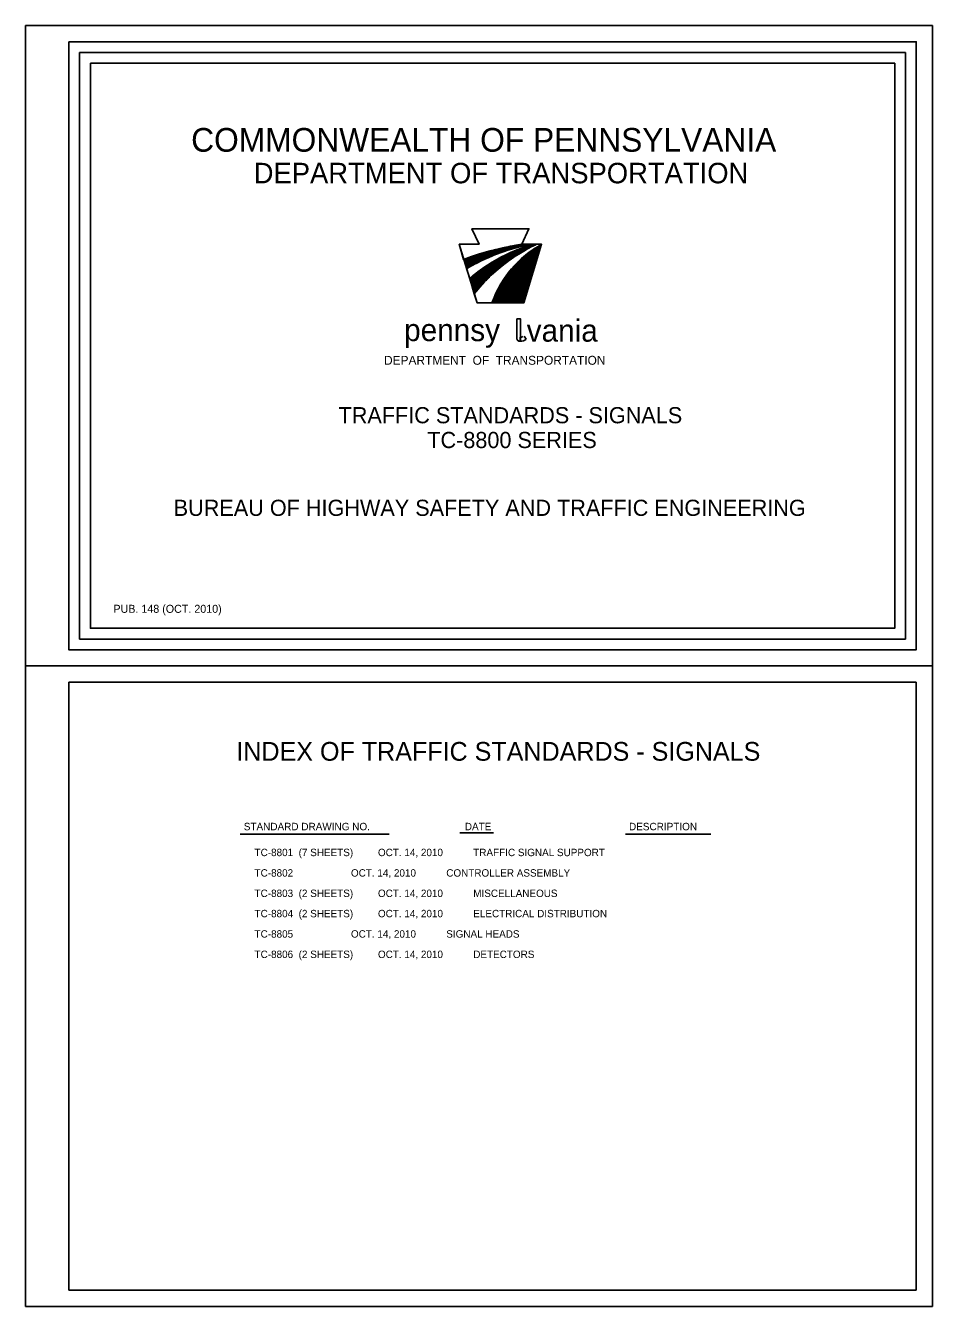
# Model space of a CAD drawing. Extents: x -1746 to -905, y 22 to 1210.
import ezdxf

# ---------------------------------------------------------------- set-up
doc = ezdxf.new("R2010")
doc.units = 0
for name, color, linetype in [('1', 7, 'Continuous'), ('2', 7, 'Continuous'), ('PLT-BNDY', 7, 'Continuous')]:
    doc.layers.add(name, color=color, linetype=linetype)

msp = doc.modelspace()

# ---------------------------------------------------------------- linework, layer by layer
at = {"layer": '1'}
for p, q in [((-1325.5, 1007.3), (-1332.2, 1021.7)), ((-1332.2, 1021.7), (-1279.3, 1021.7)), ((-1279.3, 1021.7), (-1286, 1007.3)), ((-1327.3, 952.9), (-1344, 1007.3)), ((-1344, 1007.3), (-1325.5, 1007.3)), ((-1286, 1007.3), (-1267.6, 1007.3)), ((-1267.6, 1007.3), (-1284.2, 952.9)), ((-1284.2, 952.9), (-1327.3, 952.9)), ((-1706.1, 601.2), (-920.1, 601.2)), ((-1706.1, 37.2), (-1706.1, 601.2)), ((-920.1, 601.2), (-920.1, 37.2)), ((-920.1, 37.2), (-1706.1, 37.2))]:
    msp.add_line(p, q, dxfattribs=at)
for points in [[(-1706.1, 1195.2), (-920.1, 1195.2), (-920.1, 631.2), (-1706.1, 631.2)], [(-1696.1, 1185.2), (-930.1, 1185.2), (-930.1, 641.2), (-1696.1, 641.2)], [(-1686.1, 1175.2), (-940.1, 1175.2), (-940.1, 651.2), (-1686.1, 651.2)], [(-1286, 1007.3), (-1279.3, 1021.7), (-1332.2, 1021.7), (-1325.5, 1007.3), (-1344, 1007.3), (-1340.1, 993.2), (-1332.6, 996), (-1326.2, 998.1), (-1320.9, 999.7), (-1315.2, 1001.2), (-1311, 1002.3), (-1302.4, 1004.3), (-1293.9, 1006), (-1288.6, 1006.8)], [(-1286, 1007.3), (-1289.7, 1006.7), (-1293.9, 1005.9), (-1299, 1004.9), (-1303.4, 1004), (-1308.4, 1002.9), (-1314.9, 1001.2), (-1321.6, 999.4), (-1327.3, 997.6), (-1333.2, 995.7), (-1338, 993.9), (-1339.8, 993.2), (-1337, 984.8), (-1332.7, 987.4), (-1328, 989.8), (-1324.3, 991.7), (-1319.8, 993.9), (-1315.3, 995.8), (-1310.4, 997.8), (-1306.5, 999.3), (-1301.8, 1001), (-1297.2, 1002.4), (-1291.9, 1004), (-1287.6, 1005.2), (-1282.8, 1006.3), (-1279.5, 1007.3)], [(-1279.5, 1007.3), (-1288.1, 1005.1), (-1299.7, 1001.6), (-1309.4, 998.2), (-1318, 994.7), (-1327.6, 990.2), (-1335.1, 986.1), (-1337.3, 984.8), (-1334.2, 975.5), (-1329.9, 979.3), (-1326.8, 981.7), (-1322.8, 984.5), (-1319.5, 986.8), (-1315.6, 989.3), (-1311, 992), (-1305.3, 995.3), (-1300.1, 997.9), (-1294.3, 1000.7), (-1291, 1001.9), (-1286.4, 1003.8), (-1280.6, 1005.7), (-1275.9, 1007.3)], [(-1275.9, 1007.3), (-1281, 1005.6), (-1285.3, 1004.1), (-1290.3, 1002.1), (-1295.5, 1000), (-1300.7, 997.6), (-1306.6, 994.5), (-1312.4, 991.2), (-1317.6, 988), (-1322.4, 984.9), (-1327.4, 981.1), (-1331.1, 978.3), (-1334.2, 975.5), (-1330.1, 961.5), (-1324.9, 967.6), (-1320.4, 972.5), (-1316.2, 976.7), (-1311.3, 981.5), (-1307.1, 985), (-1302.4, 988.9), (-1297.7, 992.5), (-1293.5, 995.4), (-1288.8, 998.3), (-1284.1, 1001.1), (-1280.8, 1003.1), (-1276.6, 1005.4), (-1272.2, 1007.3)], [(-1272.2, 1007.3), (-1276.2, 1005.6), (-1282, 1002.5), (-1289.2, 998.1), (-1297.3, 992.7), (-1304.2, 987.5), (-1308, 984.4), (-1314.3, 978.7), (-1318.1, 974.9), (-1323.2, 969.5), (-1326.5, 965.7), (-1330.1, 961.5), (-1327.3, 952.9), (-1313.4, 952.9), (-1312.6, 955.3), (-1309.9, 961.9), (-1308.2, 965.3), (-1305.3, 970.7), (-1302.6, 975), (-1299, 980.1), (-1295.4, 984.5), (-1290.7, 989.7), (-1286, 994.3), (-1281.9, 997.6), (-1278.1, 1000.7), (-1274.4, 1003.2), (-1270.2, 1005.7), (-1267.6, 1007.3)], [(-1267.6, 1007.3), (-1270.7, 1005.4), (-1274.1, 1003.3), (-1278, 1000.6), (-1282.5, 997.1), (-1286.2, 994.1), (-1289, 991.3), (-1292.4, 987.6), (-1296.4, 983.3), (-1299.7, 979.1), (-1302.6, 975), (-1305.1, 970.9), (-1307, 967.6), (-1309.5, 962.9), (-1312, 956.5), (-1313.4, 952.9), (-1284.2, 952.9)]]:
    msp.add_lwpolyline(points, close=True, dxfattribs=at)
msp.add_circle((-1294.1, 965.8), 6.84, dxfattribs=at)
for centre, radius, start, end in [((-1243, 732.1), 278.5, 98.8803, 110.3962), ((-1239.2, 816.6), 194.6, 102.171, 120.2393), ((-1230.7, 854.8), 159.1, 106.6298, 130.6117), ((-1204.9, 863.2), 159, 115.3724, 141.7165), ((-1219.7, 920.2), 99.4, 118.798, 160.3663)]:
    msp.add_arc(centre, radius, start, end, dxfattribs=at)
at = {"layer": '2'}
for p, q in [((-1338.9, 990.4), (-1325.5, 998.2)), ((-1338.5, 989.5), (-1321.2, 999.5)), ((-1338.2, 988.5), (-1317.4, 1000.5)), ((-1337.9, 987.5), (-1313.6, 1001.5)), ((-1337.6, 986.5), (-1310, 1002.5)), ((-1337.3, 985.6), (-1306.6, 1003.3)), ((-1334, 974.7), (-1279.5, 1006.1)), ((-1333.8, 975.9), (-1284.3, 1004.5)), ((-1333.7, 973.7), (-1275.4, 1007.3)), ((-1333.4, 972.7), (-1282.3, 1002.2)), ((-1329.2, 979.7), (-1290.5, 1002.1)), ((-1326.9, 990.4), (-1303.5, 1003.9)), ((-1322.7, 984.6), (-1298, 998.9)), ((-1316.2, 995.4), (-1300.2, 1004.7)), ((-1309.4, 998.2), (-1297.1, 1005.3)), ((-1303.9, 1000.2), (-1294.1, 1005.9)), ((-1299.2, 1001.8), (-1291.2, 1006.4)), ((-1296.4, 983.3), (-1270.3, 998.3)), ((-1295, 1003.1), (-1288.3, 1006.9)), ((-1294.2, 985.7), (-1269.9, 999.7)), ((-1292, 988.1), (-1269.4, 1001.1)), ((-1290.9, 1004.3), (-1285.6, 1007.3)), ((-1289.6, 990.6), (-1269, 1002.5)), ((-1287, 1005.4), (-1283.6, 1007.3)), ((-1287, 993.3), (-1268.6, 1003.9)), ((-1283.7, 1006.1), (-1281.6, 1007.3)), ((-1282.9, 996.8), (-1268.2, 1005.3)), ((-1279.8, 1003.6), (-1273.4, 1007.3)), ((-1279.6, 1007.3), (-1279.6, 1007.3)), ((-1276.1, 1001.9), (-1267.7, 1006.7)), ((-1339.4, 992.4), (-1334.9, 995)), ((-1339.2, 991.4), (-1330, 996.7)), ((-1333.1, 971.7), (-1299.7, 991)), ((-1332.8, 970.7), (-1305, 986.8)), ((-1306.7, 968.1), (-1273.7, 987.1)), ((-1305.7, 969.8), (-1273.3, 988.5)), ((-1304.7, 971.5), (-1272.9, 989.9)), ((-1303.6, 973.3), (-1272.4, 991.3)), ((-1302.5, 975.1), (-1272, 992.7)), ((-1301.2, 977.1), (-1271.6, 994.1)), ((-1299.8, 979), (-1271.2, 995.5)), ((-1298.1, 981.1), (-1270.7, 996.9)), ((-1332.5, 969.7), (-1309.5, 983)), ((-1332.2, 968.7), (-1313.1, 979.8)), ((-1331.9, 967.8), (-1316, 976.9)), ((-1331.6, 966.8), (-1318.8, 974.2)), ((-1313, 954), (-1277.6, 974.5)), ((-1312.4, 955.5), (-1277.2, 975.9)), ((-1311.8, 957), (-1276.7, 977.3)), ((-1311.2, 958.5), (-1276.3, 978.7)), ((-1310.6, 960.1), (-1275.9, 980.1)), ((-1310, 961.6), (-1275.5, 981.5)), ((-1309.3, 963.1), (-1275, 982.9)), ((-1308.5, 964.7), (-1274.6, 984.3)), ((-1307.6, 966.4), (-1274.2, 985.7)), ((-1331.3, 965.8), (-1321.3, 971.6)), ((-1331, 964.8), (-1323.5, 969.1)), ((-1330.7, 963.8), (-1325.6, 966.8)), ((-1330.4, 962.8), (-1327.6, 964.5)), ((-1312.9, 952.9), (-1278, 973.1)), ((-1310.9, 952.9), (-1278.5, 971.7)), ((-1308.9, 952.9), (-1278.9, 970.3)), ((-1306.9, 952.9), (-1279.3, 968.9)), ((-1304.9, 952.9), (-1279.7, 967.5)), ((-1302.9, 952.9), (-1280.2, 966.1)), ((-1300.9, 952.9), (-1280.6, 964.7)), ((-1298.9, 952.9), (-1281, 963.3)), ((-1330.1, 961.8), (-1329.5, 962.2)), ((-1296.9, 952.9), (-1281.5, 961.9)), ((-1294.9, 952.9), (-1281.9, 960.5)), ((-1292.9, 952.9), (-1282.3, 959.1)), ((-1290.9, 952.9), (-1282.8, 957.7)), ((-1288.9, 952.9), (-1283.2, 956.3)), ((-1286.9, 952.9), (-1283.6, 954.8)), ((-1284.9, 952.9), (-1284, 953.4)), ((-1287.5, 917.5), (-1287.4, 921.1)), ((-1287.4, 921.4), (-1286.8, 920.9)), ((-1287.4, 921.2), (-1287, 920.9)), ((-1283.8, 922.2), (-1282, 919.3)), ((-1547.3, 460.3), (-1409.1, 460.3)), ((-1343.3, 461.3), (-1312.2, 461.3)), ((-1189.9, 460.3), (-1110.5, 460.3)), ((-1533.8, 446.7), (-1533.8, 446.7)), ((-1533.8, 446.5), (-1533.8, 446.5)), ((-1533.8, 427.8), (-1533.8, 427.8)), ((-1533.8, 408.4), (-1533.8, 408.4)), ((-1533.8, 371.1), (-1533.8, 371.1)), ((-1533.8, 352.2), (-1533.8, 352.2))]:
    msp.add_line(p, q, dxfattribs=at)
msp.add_lwpolyline([(-1290.4, 938.2), (-1290.4, 919.5), (-1290, 918.3), (-1288.6, 917.4), (-1287.3, 917.4), (-1287.3, 938.2)], close=True, dxfattribs=at)
for major_axis in [(-7.26, 0), (-2.86, 0)]:
    msp.add_ellipse((-1287.2, 923.2), major_axis=major_axis, ratio=0.782967, start_param=1.534978, end_param=2.37838, dxfattribs=at)
at = {"layer": 'PLT-BNDY'}
for points in [[(-1746.1, 1210.2), (-905.1, 1210.2), (-905.1, 616.2), (-1746.1, 616.2)], [(-1746.1, 616.2), (-905.1, 616.2), (-905.1, 22.2), (-1746.1, 22.2)]]:
    msp.add_lwpolyline(points, close=True, dxfattribs=at)

# ---------------------------------------------------------------- texts
at = {"layer": '2'}
for s, height, p in [('COMMONWEALTH OF PENNSYLVANIA', 22, (-1592.6, 1093.2)), ('DEPARTMENT OF TRANSPORTATION', 19, (-1534.6, 1063.9)), ('vania', 20.63, (-1281.4, 917)), ('pennsy ', 20.63, (-1395.1, 917.5)), ('DEPARTMENT  OF  TRANSPORTATION', 8.25, (-1413.7, 895.6)), ('TRAFFIC STANDARDS - SIGNALS', 15, (-1455.9, 841.3)), ('TC-8800 SERIES', 15, (-1373.6, 818.3)), ('BUREAU OF HIGHWAY SAFETY AND TRAFFIC ENGINEERING', 15, (-1608.8, 755.4)), ('PUB. 148 (OCT. 2010)', 7.425, (-1664.7, 665.5)), ('INDEX OF TRAFFIC STANDARDS - SIGNALS', 17.397, (-1550.7, 528.3)), ('STANDARD DRAWING NO.', 6.907, (-1543.8, 463.8)), ('DATE', 6.91, (-1338.8, 463.8)), ('DESCRIPTION', 6.907, (-1186.5, 463.8)), ('TC-8801  (7 SHEETS)         OCT. 14, 2010           TRAFFIC SIGNAL SUPPORT', 6.875, (-1533.8, 439.8)), ('TC-8802                     OCT. 14, 2010           CONTROLLER ASSEMBLY', 6.875, (-1533.8, 420.8)), ('TC-8803  (2 SHEETS)         OCT. 14, 2010           MISCELLANEOUS', 6.875, (-1533.8, 401.9)), ('TC-8804  (2 SHEETS)         OCT. 14, 2010           ELECTRICAL DISTRIBUTION', 6.875, (-1533.8, 383.1)), ('TC-8805                     OCT. 14, 2010           SIGNAL HEADS', 6.875, (-1533.8, 364.2)), ('TC-8806  (2 SHEETS)         OCT. 14, 2010           DETECTORS', 6.875, (-1533.8, 345.3))]:
    msp.add_text(s, height=height, dxfattribs=at).set_placement(p)

doc.saveas('drawing.dxf')
